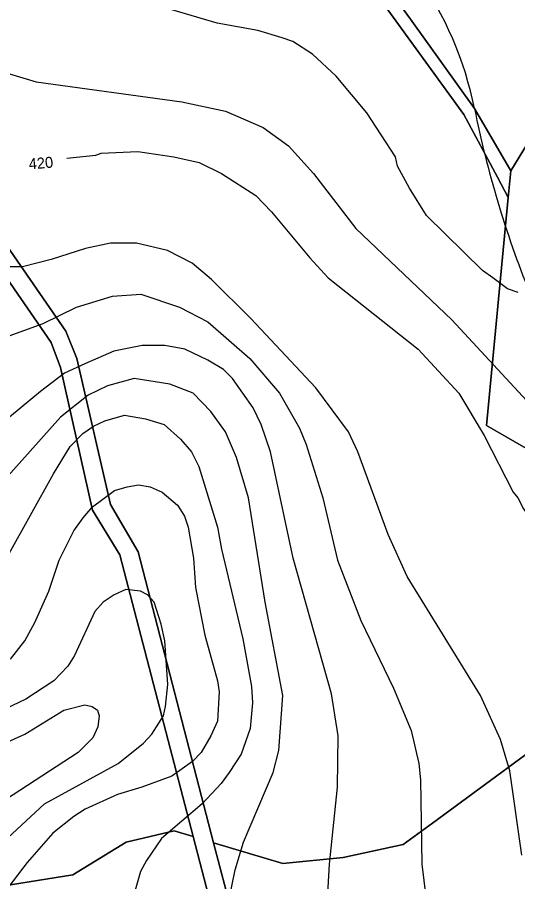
# Model space of a CAD drawing. Extents: x -510989 to -501240, y -1184665 to -1176089.
# Drawn here: x -504887.1 to -504614, y -1179549.5 to -1179077.8 of the extents above; entities that cross this region are included whole.
import ezdxf

# ---------------------------------------------------------------- set-up
doc = ezdxf.new("R2010")
doc.units = 0
for name, color, linetype in [('lesni_pozemek', 7, 'Continuous'), ('NAVRH_rozvodnice', 7, 'Continuous'), ('ostatni_plocha_x_jina_plocha', 7, 'Continuous'), ('ostatni_plocha_x_ostatni_komunikace', 7, 'Continuous'), ('STAV_povodi', 7, 'Continuous'), ('vrstevnice_01', 7, 'Continuous'), ('vrstevnice_02', 7, 'Continuous'), ('vrstevnice_04', 7, 'Continuous')]:
    doc.layers.add(name, color=color, linetype=linetype)

msp = doc.modelspace()

# ---------------------------------------------------------------- linework, layer by layer
at = {"layer": 'lesni_pozemek'}
for points in [[(-504534.21, -1179067.72), (-504542.42, -1179143.48), (-504602.14, -1179135.92), (-504617.86, -1179161.64), (-504637.61, -1179127.69), (-504672.6, -1179078.92), (-504775.12, -1178938.48)], [(-504754.78, -1178977.35), (-504643.42, -1179130.79), (-504625.14, -1179165.11), (-504619.23, -1179176.18), (-504630.98, -1179300.63), (-504594.1, -1179321.87), (-504555.62, -1179312.32), (-504564.44, -1179393.84), (-504582.14, -1179455.19), (-504597.17, -1179471.07), (-504660.52, -1179517.57), (-504676.61, -1179529.31), (-504709.29, -1179536.25), (-504742.19, -1179539.68), (-504779.97, -1179528.31), (-504821.2, -1179369.58), (-504836.21, -1179343.71), (-504854.66, -1179264.06), (-504860.72, -1179249.16), (-504952.9, -1179115.84), (-504922.16, -1179078.43), (-504889.19, -1179027.53)]]:
    msp.add_lwpolyline(points, dxfattribs=at)
for points in [[(-504954.27, -1179117.63), (-504952.9, -1179115.84), (-504860.72, -1179249.16), (-504854.66, -1179264.06), (-504836.21, -1179343.71), (-504821.2, -1179369.58), (-504779.97, -1179528.31), (-504769.76, -1179567.61), (-504727.86, -1179711.51), (-504708.41, -1179767.57), (-504707.28, -1179770.82), (-504709.21, -1179772.58), (-504712.88, -1179775.94), (-504714.09, -1179772.21), (-504716.55, -1179774.62), (-504737.74, -1179713.52), (-504779.19, -1179571.1), (-504791.18, -1179524.93), (-504831.12, -1179371.17), (-504846.08, -1179346.72), (-504863.52, -1179268.91), (-504868.59, -1179255.37), (-504959.28, -1179124.19), (-504958.33, -1179122.95)], [(-504959.28, -1179124.19), (-504868.59, -1179255.37), (-504863.52, -1179268.91), (-504846.08, -1179346.72), (-504831.12, -1179371.17), (-504791.18, -1179524.93), (-504801.54, -1179521.81), (-504827.69, -1179527.9), (-504856.8, -1179545.69), (-504909.19, -1179554.06), (-504918, -1179530), (-504946, -1179426), (-504964, -1179378.01), (-504974.14, -1179381.87), (-505011.79, -1179313.59), (-505062.3, -1179220.25), (-505044.57, -1179207.26), (-504990.8, -1179163.24), (-504973.1, -1179140.81)], [(-504582.14, -1179455.19), (-504586.07, -1179468.8), (-504591.62, -1179551.19), (-504628.66, -1179661.64), (-504630.09, -1179676.65), (-504638.55, -1179681.74), (-504680.7, -1179742.43), (-504708.41, -1179767.57), (-504727.86, -1179711.51), (-504769.76, -1179567.61), (-504779.97, -1179528.31), (-504742.19, -1179539.68), (-504709.29, -1179536.25), (-504676.61, -1179529.31), (-504660.52, -1179517.57), (-504597.17, -1179471.07)], [(-504791.18, -1179524.93), (-504779.19, -1179571.1), (-504737.74, -1179713.52), (-504716.55, -1179774.62), (-504798.62, -1179856.09), (-504835.94, -1179754.53), (-504909.19, -1179554.06), (-504856.8, -1179545.69), (-504827.69, -1179527.9), (-504801.54, -1179521.81)]]:
    msp.add_lwpolyline(points, close=True, dxfattribs=at)
at = {"layer": 'NAVRH_rozvodnice'}
for centre, radius, start, end in [((-504826.23, -1179165.58), 192.39, 11.3573, 58.8068), ((-504082.32, -1179016.15), 566.38, 191.3573, 201.9647)]:
    msp.add_arc(centre, radius, start, end, dxfattribs=at)
at = {"layer": 'ostatni_plocha_x_jina_plocha'}
msp.add_lwpolyline([(-504594.1, -1179321.87), (-504630.98, -1179300.63), (-504619.23, -1179176.18), (-504617.86, -1179161.64), (-504602.14, -1179135.92)], dxfattribs=at)
at = {"layer": 'ostatni_plocha_x_ostatni_komunikace'}
msp.add_lwpolyline([(-504775.12, -1178938.48), (-504672.6, -1179078.92), (-504637.61, -1179127.69), (-504617.86, -1179161.64), (-504619.23, -1179176.18), (-504625.14, -1179165.11), (-504643.42, -1179130.79), (-504754.78, -1178977.35)], dxfattribs=at)
at = {"layer": 'STAV_povodi'}
for centre, radius, start, end in [((-504826.23, -1179165.58), 192.39, 11.3573, 58.8068), ((-504082.32, -1179016.15), 566.38, 191.3573, 201.9647)]:
    msp.add_arc(centre, radius, start, end, dxfattribs=at)
at = {"layer": 'vrstevnice_01'}
for points in [[(-504613.69, -1179228), (-504619.59, -1179226), (-504627.69, -1179220), (-504633.31, -1179216), (-504663.81, -1179186), (-504673.09, -1179171), (-504679.69, -1179159), (-504680.69, -1179154), (-504696.31, -1179130), (-504713.09, -1179110), (-504726.09, -1179098), (-504736.69, -1179091), (-504742.5, -1179089), (-504755.81, -1179085), (-504778, -1179081), (-504821.81, -1179068)], [(-504860.06, -1179154.7), (-504844.31, -1179153), (-504841.41, -1179152), (-504821.31, -1179151), (-504801.69, -1179154), (-504787.81, -1179157), (-504775.59, -1179163), (-504757, -1179175), (-504748.31, -1179184), (-504727.41, -1179209), (-504717.41, -1179220), (-504668.31, -1179259), (-504646.09, -1179283), (-504632.31, -1179306), (-504616.5, -1179337), (-504614, -1179340), (-504610.81, -1179346), (-504581.91, -1179388), (-504565.81, -1179416), (-504547.31, -1179439), (-504537, -1179466)], [(-504903.81, -1179256), (-504873.09, -1179245), (-504854.81, -1179236), (-504835.09, -1179230), (-504819.69, -1179229), (-504798.59, -1179236), (-504783.09, -1179244), (-504760.19, -1179264), (-504744, -1179283), (-504733.19, -1179302), (-504729.41, -1179311), (-504720.31, -1179340), (-504712.31, -1179374), (-504699.59, -1179407), (-504681.81, -1179444), (-504672.09, -1179467), (-504668, -1179485), (-504667.09, -1179494), (-504666.31, -1179540), (-504661.81, -1179577)], [(-504771.5, -1179559), (-504768.31, -1179543), (-504763.69, -1179528), (-504747.5, -1179490), (-504744.41, -1179478), (-504742.19, -1179448), (-504751.81, -1179397), (-504760.91, -1179340), (-504767.41, -1179318), (-504773.5, -1179304), (-504781.5, -1179293), (-504791.19, -1179283), (-504803.91, -1179278), (-504823.41, -1179275), (-504837.81, -1179279), (-504848.41, -1179284), (-504863.59, -1179296), (-504907.41, -1179345)], [(-504890.91, -1179428), (-504883, -1179418), (-504877.59, -1179408), (-504870, -1179391), (-504864.31, -1179374), (-504856.19, -1179358), (-504851.19, -1179351), (-504846, -1179345), (-504834, -1179336), (-504827.19, -1179334), (-504821, -1179333), (-504814.69, -1179334), (-504808.09, -1179337), (-504799.69, -1179344), (-504795.81, -1179350), (-504793.81, -1179356), (-504790.91, -1179373), (-504789.81, -1179389), (-504784.81, -1179415), (-504777.91, -1179440), (-504777, -1179446), (-504777.81, -1179462), (-504781.41, -1179470), (-504786.81, -1179479), (-504791.59, -1179484), (-504802.81, -1179492), (-504819.09, -1179498), (-504832.5, -1179502), (-504850, -1179510), (-504856.19, -1179514), (-504867.69, -1179523), (-504881.81, -1179539), (-504897.19, -1179559)], [(-505063.5, -1179448), (-505032.31, -1179476), (-505018.31, -1179483), (-505001.31, -1179487), (-504989.19, -1179487), (-504964.41, -1179485), (-504915.69, -1179479), (-504902.59, -1179477), (-504896.31, -1179475), (-504883, -1179469), (-504861.69, -1179456), (-504850.31, -1179453), (-504846.31, -1179454), (-504843.41, -1179456), (-504842.5, -1179459), (-504843.09, -1179465), (-504845.91, -1179471), (-504853.91, -1179479), (-504929.19, -1179528), (-504944.41, -1179536), (-504962.31, -1179547), (-504971.09, -1179555)]]:
    msp.add_lwpolyline(points, dxfattribs=at)
at = {"layer": 'vrstevnice_02'}
for points in [[(-505001.59, -1179039), (-504941.81, -1179083), (-504914.81, -1179100), (-504900.59, -1179106), (-504876.91, -1179113), (-504797.41, -1179124), (-504773.41, -1179129), (-504753, -1179138), (-504739.09, -1179148), (-504725.41, -1179163), (-504702.41, -1179193), (-504649.91, -1179243), (-504604.5, -1179292)], [(-504611.81, -1179535), (-504618.31, -1179489), (-504623.5, -1179472), (-504634.31, -1179448), (-504674.31, -1179383), (-504684.69, -1179360), (-504701.19, -1179315), (-504706.41, -1179304), (-504724.19, -1179280), (-504759.81, -1179242), (-504781.09, -1179221), (-504791.69, -1179212), (-504805.19, -1179205), (-504822.09, -1179201), (-504836.31, -1179201), (-504849.81, -1179204), (-504868.59, -1179210), (-504884.19, -1179214), (-504896.5, -1179214)], [(-504715.59, -1179447), (-504736.59, -1179373), (-504748.91, -1179315), (-504754.09, -1179300), (-504758.31, -1179291), (-504769.59, -1179275), (-504774.5, -1179270), (-504783.09, -1179265), (-504795.69, -1179259), (-504806.69, -1179257), (-504818.91, -1179257), (-504834.41, -1179260), (-504850.31, -1179267), (-504861.31, -1179272), (-504874.41, -1179282), (-504891.31, -1179296)], [(-504892.41, -1179372), (-504867.31, -1179327), (-504858.31, -1179312), (-504851.31, -1179305), (-504845.5, -1179301), (-504839.41, -1179298), (-504828.69, -1179295), (-504817.19, -1179297), (-504807, -1179300), (-504798, -1179308), (-504792.09, -1179315), (-504788, -1179323), (-504777.81, -1179356), (-504775.69, -1179368), (-504764, -1179417), (-504759.31, -1179443), (-504758.69, -1179452), (-504760.09, -1179466), (-504765, -1179480), (-504771.41, -1179490), (-504775.81, -1179496), (-504786.19, -1179507), (-504808.5, -1179526), (-504816.69, -1179538), (-504819.81, -1179544), (-504823.81, -1179558)], [(-504894.81, -1179528), (-504872.19, -1179507), (-504832, -1179485), (-504818.31, -1179474), (-504813.69, -1179469), (-504807.41, -1179459), (-504806.19, -1179454), (-504805, -1179442), (-504806.69, -1179418), (-504808.59, -1179409), (-504812.5, -1179397), (-504816, -1179393), (-504819.81, -1179391), (-504827.91, -1179390), (-504834.19, -1179393), (-504840.19, -1179397), (-504844.81, -1179402), (-504855.91, -1179426), (-504859.59, -1179432), (-504867.19, -1179440), (-504882.5, -1179450), (-504897.59, -1179457)], [(-504611.31, -1179873), (-504620.81, -1179851), (-504632.69, -1179830), (-504640.81, -1179814), (-504647.59, -1179795), (-504656.09, -1179757), (-504657, -1179748), (-504663.31, -1179717), (-504667.31, -1179701), (-504677.59, -1179674), (-504685.91, -1179654), (-504698.91, -1179629), (-504709.59, -1179602), (-504715.09, -1179577), (-504717.81, -1179559), (-504716.81, -1179540), (-504712.41, -1179498), (-504712.09, -1179470), (-504715.59, -1179447)]]:
    msp.add_lwpolyline(points, dxfattribs=at)

# ---------------------------------------------------------------- texts
at = {"layer": 'vrstevnice_04'}
msp.add_text('420', height=6, rotation=4.9033, dxfattribs=at).set_placement((-504880.66, -1179160.94))

doc.saveas('drawing.dxf')
